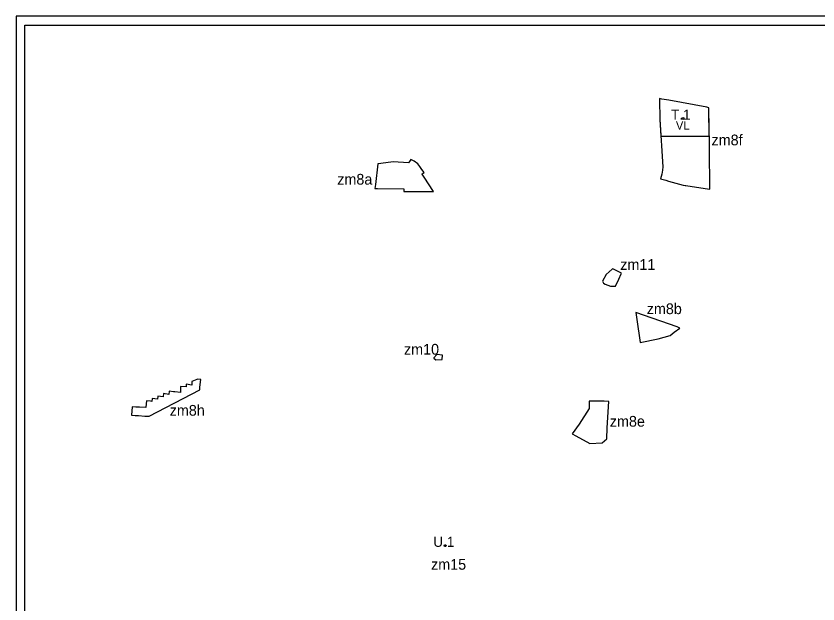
# Model space of a CAD drawing. Extents: x -555210 to -552521, y -1185897 to -1183927.
# Drawn here: x -555210 to -553865, y -1184912 to -1183927 of the extents above; entities that cross this region are included whole.
import ezdxf

# ---------------------------------------------------------------- set-up
doc = ezdxf.new("R2010")
doc.units = 0
for name, color, linetype in [('LEG_2b', 7, 'Continuous'), ('MISTNI_KOMUNIKACE_stav', 7, 'Continuous'), ('navrh_PU', 7, 'Continuous'), ('OBRYS_PLOCH', 7, 'Continuous'), ('ram_5000', 7, 'Continuous'), ('stav_OV', 7, 'Continuous'), ('stav_PU', 7, 'Continuous'), ('stav_SV', 7, 'Continuous'), ('stav_ZZ', 7, 'Continuous')]:
    doc.layers.add(name, color=color, linetype=linetype)

msp = doc.modelspace()

# ---------------------------------------------------------------- linework, layer by layer
at = {"layer": 'LEG_2b'}
msp.add_circle((-554091.6, -1184098.7), 1.64, dxfattribs=at)
at = {"layer": 'MISTNI_KOMUNIKACE_stav'}
msp.add_circle((-554490.4, -1184814.5), 1.64, dxfattribs=at)
at = {"layer": 'navrh_PU'}
for p, q in [((-554130.8, -1184065.3), (-554130.9, -1184066.6)), ((-554130.8, -1184065.3), (-554130.9, -1184066.6)), ((-554130.8, -1184065.3), (-554130.9, -1184066.6)), ((-554130.9, -1184066.6), (-554130.6, -1184100.4)), ((-554130.9, -1184066.6), (-554130.6, -1184100.4)), ((-554130.9, -1184066.6), (-554130.6, -1184100.4)), ((-554127.1, -1184066), (-554130.8, -1184065.3)), ((-554127.1, -1184066), (-554130.8, -1184065.3)), ((-554127.1, -1184066), (-554130.8, -1184065.3)), ((-554115.6, -1184068.1), (-554127.1, -1184066)), ((-554115.6, -1184068.1), (-554127.1, -1184066)), ((-554115.6, -1184068.1), (-554127.1, -1184066)), ((-554051.7, -1184079.9), (-554115.6, -1184068.1)), ((-554051.7, -1184079.9), (-554115.6, -1184068.1)), ((-554051.7, -1184079.9), (-554115.6, -1184068.1)), ((-554048.2, -1184080.6), (-554051.7, -1184079.9)), ((-554048.2, -1184080.6), (-554051.7, -1184079.9)), ((-554048.2, -1184080.6), (-554051.7, -1184079.9)), ((-554048.1, -1184084.3), (-554048.2, -1184080.6)), ((-554048.1, -1184084.3), (-554048.2, -1184080.6)), ((-554048.1, -1184084.3), (-554048.2, -1184080.6)), ((-554047.6, -1184127.4), (-554048.1, -1184084.3)), ((-554047.6, -1184127.4), (-554048.1, -1184084.3)), ((-554047.6, -1184127.4), (-554048.1, -1184084.3)), ((-554130.6, -1184100.4), (-554128.7, -1184128.5)), ((-554130.6, -1184100.4), (-554128.7, -1184128.5)), ((-554130.6, -1184100.4), (-554128.7, -1184128.5)), ((-554128.7, -1184128.5), (-554047.5, -1184128.5)), ((-554128.7, -1184128.5), (-554047.5, -1184128.5)), ((-554128.7, -1184128.5), (-554047.5, -1184128.5)), ((-554047.5, -1184128.5), (-554047.6, -1184127.4)), ((-554047.5, -1184128.5), (-554047.6, -1184127.4)), ((-554047.5, -1184128.5), (-554047.6, -1184127.4))]:
    msp.add_line(p, q, dxfattribs=at)
at = {"layer": 'ram_5000'}
for p, q in [((-554130.8, -1184065.3), (-554130.9, -1184066.6)), ((-554130.9, -1184066.6), (-554130.6, -1184100.4)), ((-554127.1, -1184066), (-554130.8, -1184065.3)), ((-554115.6, -1184068.1), (-554127.1, -1184066)), ((-554051.7, -1184079.9), (-554115.6, -1184068.1)), ((-554048.2, -1184080.6), (-554051.7, -1184079.9)), ((-554048.1, -1184084.3), (-554048.2, -1184080.6)), ((-554047.4, -1184141.4), (-554048.1, -1184084.3)), ((-554130.6, -1184100.4), (-554125.3, -1184179.6)), ((-554047.2, -1184151.8), (-554047.4, -1184141.4)), ((-554046.5, -1184214.4), (-554047.2, -1184151.8)), ((-554550.3, -1184170.9), (-554551.9, -1184173.2)), ((-554549.1, -1184169.1), (-554550.3, -1184170.9)), ((-554547.8, -1184167.2), (-554549.1, -1184169.1)), ((-554542.4, -1184170.4), (-554547.8, -1184167.2)), ((-554536.1, -1184174.5), (-554542.4, -1184170.4)), ((-554603, -1184174.5), (-554607.4, -1184209)), ((-554598.3, -1184173.9), (-554603, -1184174.5)), ((-554577.5, -1184171.2), (-554598.3, -1184173.9)), ((-554551.9, -1184173.2), (-554577.5, -1184171.2)), ((-554125.3, -1184179.6), (-554126.2, -1184185.4)), ((-554529, -1184191.9), (-554528.7, -1184191.7)), ((-554525.5, -1184196.7), (-554529, -1184191.9)), ((-554528.8, -1184191.5), (-554527.2, -1184190.3)), ((-554528.7, -1184191.7), (-554528.8, -1184191.5)), ((-554527.2, -1184190.3), (-554525.8, -1184189.3)), ((-554509.9, -1184220.8), (-554525.5, -1184196.7)), ((-554127.2, -1184192.2), (-554129.3, -1184199.7)), ((-554126.2, -1184185.4), (-554127.2, -1184192.2)), ((-554607.4, -1184209), (-554608.3, -1184215.8)), ((-554129.3, -1184199.7), (-554120.6, -1184202.2)), ((-554120.6, -1184202.2), (-554115.9, -1184203.5)), ((-554115.9, -1184203.5), (-554091.2, -1184210.2)), ((-554091.2, -1184210.2), (-554088.1, -1184210.7)), ((-554088.1, -1184210.7), (-554086.8, -1184210.9)), ((-554086.8, -1184210.9), (-554054.4, -1184215.9)), ((-554559.9, -1184220.8), (-554535.4, -1184220.8)), ((-554535.4, -1184220.8), (-554526.4, -1184220.8)), ((-554526.4, -1184220.8), (-554519.6, -1184220.8)), ((-554519.6, -1184220.8), (-554509.9, -1184220.8)), ((-554054.4, -1184215.9), (-554046.5, -1184217.2)), ((-554046.5, -1184217.2), (-554046.5, -1184214.4)), ((-554194.8, -1184358), (-554209.4, -1184350.6)), ((-554195.3, -1184359), (-554194.8, -1184358)), ((-554220.3, -1184359.8), (-554226.4, -1184371)), ((-554226.4, -1184371), (-554225.1, -1184374.6)), ((-554225.1, -1184374.6), (-554221.8, -1184376)), ((-554221.8, -1184376), (-554213.4, -1184379.5)), ((-554213.4, -1184379.5), (-554212, -1184379.5)), ((-554212, -1184379.5), (-554206.8, -1184379.5)), ((-554206.8, -1184379.5), (-554206.1, -1184379.5)), ((-554206.1, -1184379.5), (-554204.6, -1184379.6)), ((-554170.7, -1184423.5), (-554169, -1184435.6)), ((-554101.4, -1184447.6), (-554170.7, -1184423.5)), ((-554169, -1184435.6), (-554163.2, -1184474.1)), ((-554106.2, -1184456.9), (-554096.8, -1184449.9)), ((-554096.8, -1184449.9), (-554101.4, -1184447.6)), ((-554133, -1184467.8), (-554113.2, -1184462.4)), ((-554113.2, -1184462.4), (-554106.2, -1184456.9)), ((-554163.2, -1184474.1), (-554133, -1184467.8)), ((-554504.4, -1184494.3), (-554509.6, -1184499.8)), ((-554509.6, -1184499.8), (-554509.2, -1184500.2)), ((-554509.2, -1184500.2), (-554506, -1184503.2)), ((-554506, -1184503.2), (-554495.6, -1184502.6)), ((-554494.9, -1184495.2), (-554504.4, -1184494.3)), ((-554495.6, -1184502.6), (-554494.9, -1184495.2)), ((-554924.5, -1184543.6), (-554924.6, -1184548.5)), ((-554905.5, -1184535.6), (-554906.8, -1184536.1)), ((-554899.8, -1184536.1), (-554905.5, -1184535.6)), ((-554901.8, -1184549.1), (-554899.8, -1184536.1)), ((-554945.6, -1184556.6), (-554952.9, -1184555.7)), ((-554943.6, -1184556.8), (-554945.6, -1184556.6)), ((-554924.6, -1184548.5), (-554933.9, -1184547.7)), ((-554933.9, -1184547.7), (-554933.9, -1184552.8)), ((-554901.9, -1184553.4), (-554901.8, -1184549.1)), ((-554984.4, -1184572.6), (-554990.8, -1184571.8)), ((-554981.9, -1184572.9), (-554984.4, -1184572.6)), ((-554971.8, -1184563.8), (-554972.4, -1184568.9)), ((-554962.9, -1184564.9), (-554971.8, -1184563.8)), ((-554248.9, -1184572.1), (-554249.1, -1184584.5)), ((-554224, -1184572.5), (-554248.9, -1184572.1)), ((-554216.1, -1184572.7), (-554224, -1184572.5)), ((-555014.9, -1184581.9), (-555016.4, -1184595.9)), ((-555008.7, -1184582.3), (-555014.9, -1184581.9)), ((-554277.2, -1184626.8), (-554271.1, -1184630.2)), ((-554271.1, -1184630.2), (-554247.5, -1184643.4)), ((-554227, -1184642.4), (-554219.5, -1184635.3)), ((-554247.5, -1184643.4), (-554227, -1184642.4))]:
    msp.add_line(p, q, dxfattribs=at)
for points in [[(-554525.8, -1184189.3), (-554529.4, -1184184), (-554532.8, -1184179.3), (-554536.1, -1184174.5)], [(-554608.3, -1184215.8), (-554603.8, -1184216.1), (-554559.9, -1184216.7), (-554559.9, -1184220.8)], [(-554209.4, -1184350.6), (-554210.2, -1184351.3), (-554220.3, -1184359.8)], [(-554204.6, -1184379.6), (-554199.3, -1184367.8), (-554195.3, -1184359)], [(-554906.8, -1184536.1), (-554915, -1184539.6), (-554914.9, -1184545.5), (-554924.5, -1184543.6)], [(-555016.4, -1184595.9), (-555010, -1184596.3), (-555004.5, -1184596.5), (-554993.7, -1184597.2), (-554986.7, -1184597.5), (-554901.9, -1184553.4)], [(-554952.9, -1184555.7), (-554953.4, -1184560.9), (-554962.4, -1184559.7), (-554962.9, -1184564.9)], [(-554933.9, -1184555.4), (-554933.9, -1184557.9), (-554943.6, -1184556.8)], [(-554933.9, -1184552.8), (-554933.9, -1184554.3), (-554933.9, -1184555.4)], [(-554990.8, -1184571.8), (-554991.4, -1184576.9), (-554992.1, -1184583.2)], [(-554972.4, -1184568.9), (-554981.3, -1184567.8), (-554981.9, -1184572.9)], [(-554219.5, -1184635.3), (-554218.5, -1184617), (-554216.1, -1184572.7)], [(-554992.1, -1184583.2), (-555003, -1184582.6), (-555008.7, -1184582.3)], [(-554249.1, -1184584.5), (-554265.4, -1184610.9), (-554277.2, -1184626.8)]]:
    msp.add_lwpolyline(points, dxfattribs=at)
at = {"layer": 'stav_OV'}
for p, q in [((-552520.8, -1183927), (-555209.8, -1183927)), ((-555209.8, -1183927), (-555209.8, -1185897.3)), ((-555194.8, -1185882.3), (-555194.8, -1183942)), ((-555194.8, -1183942), (-553535.8, -1183942))]:
    msp.add_line(p, q, dxfattribs=at)
at = {"layer": 'stav_ZZ'}
for p, q in [((-554130.8, -1184065.3), (-554130.9, -1184066.6)), ((-554130.9, -1184066.6), (-554130.6, -1184100.4)), ((-554127.1, -1184066), (-554130.8, -1184065.3)), ((-554115.6, -1184068.1), (-554127.1, -1184066)), ((-554051.7, -1184079.9), (-554115.6, -1184068.1)), ((-554048.2, -1184080.6), (-554051.7, -1184079.9)), ((-554048.1, -1184084.3), (-554048.2, -1184080.6)), ((-554047.6, -1184127.4), (-554048.1, -1184084.3)), ((-554130.6, -1184100.4), (-554128.7, -1184128.5)), ((-554128.7, -1184128.5), (-554047.5, -1184128.5)), ((-554047.5, -1184128.5), (-554047.6, -1184127.4))]:
    msp.add_line(p, q, dxfattribs=at)

# ---------------------------------------------------------------- texts
at = {"layer": 'MISTNI_KOMUNIKACE_stav'}
for s, height, p in [('U.1', 17, (-554510.2, -1184816.5)), ('zm15', 18, (-554514, -1184854.8))]:
    msp.add_text(s, height=height, dxfattribs=at).set_placement(p)
at = {"layer": 'OBRYS_PLOCH'}
msp.add_text('VL', height=14, dxfattribs=at).set_placement((-554103.5, -1184117.2))
at = {"layer": 'stav_PU'}
msp.add_text('T.1', height=17, dxfattribs=at).set_placement((-554111.7, -1184100.7))
at = {"layer": 'stav_SV'}
for s, p in [('zm8f', (-554043.8, -1184143.6)), ('zm8a', (-554671.3, -1184209.5)), ('zm11', (-554196.8, -1184352.3)), ('zm8b', (-554152.4, -1184426.5)), ('zm10', (-554559.4, -1184494.4)), ('zm8h', (-554952.2, -1184596.7)), ('zm8e', (-554214.3, -1184615.1))]:
    msp.add_text(s, height=18, dxfattribs=at).set_placement(p)

doc.saveas('drawing.dxf')
